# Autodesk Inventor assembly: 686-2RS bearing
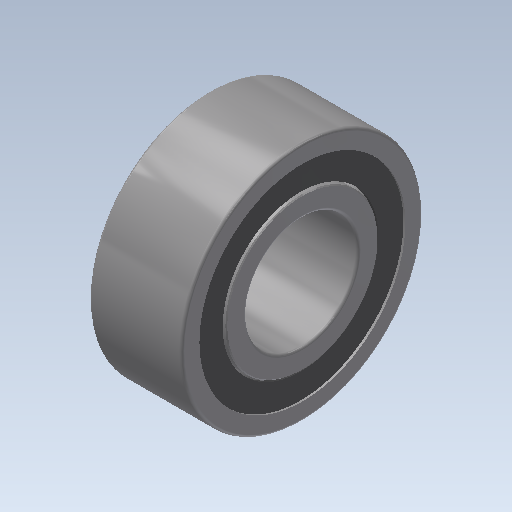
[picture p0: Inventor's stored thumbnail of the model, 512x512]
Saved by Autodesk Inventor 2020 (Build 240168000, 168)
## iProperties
Created: 2017-11
Part Number: 686-2RS bearing
Material: Ogólny
Document SubType Name: Assembly
Designer: Tomasz
Sending System: SolidWorks 2017
Last Author: Tomasz
Last Saved: 2017-11-19
Source: 686-2rs
Author: Tomasz
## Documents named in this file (13)
- C:\Users\bruno\Documents\1-Cours-2020-21\1STI2D-2020-21\IT\6. Antivol\Inventor-Antivol\INVENTOR 2018_Steel Hardtail B+\686-2RS bearing.iam
- C:\Users\bruno\Documents\1-Cours-2020-21\1STI2D-2020-21\IT\6. Antivol\Inventor-Antivol\INVENTOR 2018_Steel Hardtail B+\686-2Z_12_1.ipt
- C:\Users\bruno\Documents\1-Cours-2020-21\1STI2D-2020-21\IT\6. Antivol\Inventor-Antivol\INVENTOR 2018_Steel Hardtail B+\686-2Z_11_1.ipt
- C:\Users\bruno\Documents\1-Cours-2020-21\1STI2D-2020-21\IT\6. Antivol\Inventor-Antivol\INVENTOR 2018_Steel Hardtail B+\686-2Z_10_1.ipt
- C:\Users\bruno\Documents\1-Cours-2020-21\1STI2D-2020-21\IT\6. Antivol\Inventor-Antivol\INVENTOR 2018_Steel Hardtail B+\686-2Z_09_1.ipt
- C:\Users\bruno\Documents\1-Cours-2020-21\1STI2D-2020-21\IT\6. Antivol\Inventor-Antivol\INVENTOR 2018_Steel Hardtail B+\686-2Z_08_1.ipt
- C:\Users\bruno\Documents\1-Cours-2020-21\1STI2D-2020-21\IT\6. Antivol\Inventor-Antivol\INVENTOR 2018_Steel Hardtail B+\686-2Z_07_1.ipt
- C:\Users\bruno\Documents\1-Cours-2020-21\1STI2D-2020-21\IT\6. Antivol\Inventor-Antivol\INVENTOR 2018_Steel Hardtail B+\686-2Z_06_1.ipt
- C:\Users\bruno\Documents\1-Cours-2020-21\1STI2D-2020-21\IT\6. Antivol\Inventor-Antivol\INVENTOR 2018_Steel Hardtail B+\686-2Z_05_1.ipt
- C:\Users\bruno\Documents\1-Cours-2020-21\1STI2D-2020-21\IT\6. Antivol\Inventor-Antivol\INVENTOR 2018_Steel Hardtail B+\686-2Z_04_1.ipt
- C:\Users\bruno\Documents\1-Cours-2020-21\1STI2D-2020-21\IT\6. Antivol\Inventor-Antivol\INVENTOR 2018_Steel Hardtail B+\686-2Z_03_1.ipt
- C:\Users\bruno\Documents\1-Cours-2020-21\1STI2D-2020-21\IT\6. Antivol\Inventor-Antivol\INVENTOR 2018_Steel Hardtail B+\686-2Z_02_1.ipt
- C:\Users\bruno\Documents\1-Cours-2020-21\1STI2D-2020-21\IT\6. Antivol\Inventor-Antivol\INVENTOR 2018_Steel Hardtail B+\686-2Z_01_1.ipt
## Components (12 placed, 12 different names)
1. 686-2Z_12_1:1
2. 686-2Z_11_1:1
3. 686-2Z_10_1:1
4. 686-2Z_09_1:1
5. 686-2Z_08_1:1
6. 686-2Z_07_1:1
7. 686-2Z_06_1:1
8. 686-2Z_05_1:1
9. 686-2Z_04_1:1
10. 686-2Z_03_1:1
11. 686-2Z_02_1:1
12. 686-2Z_01_1:1
